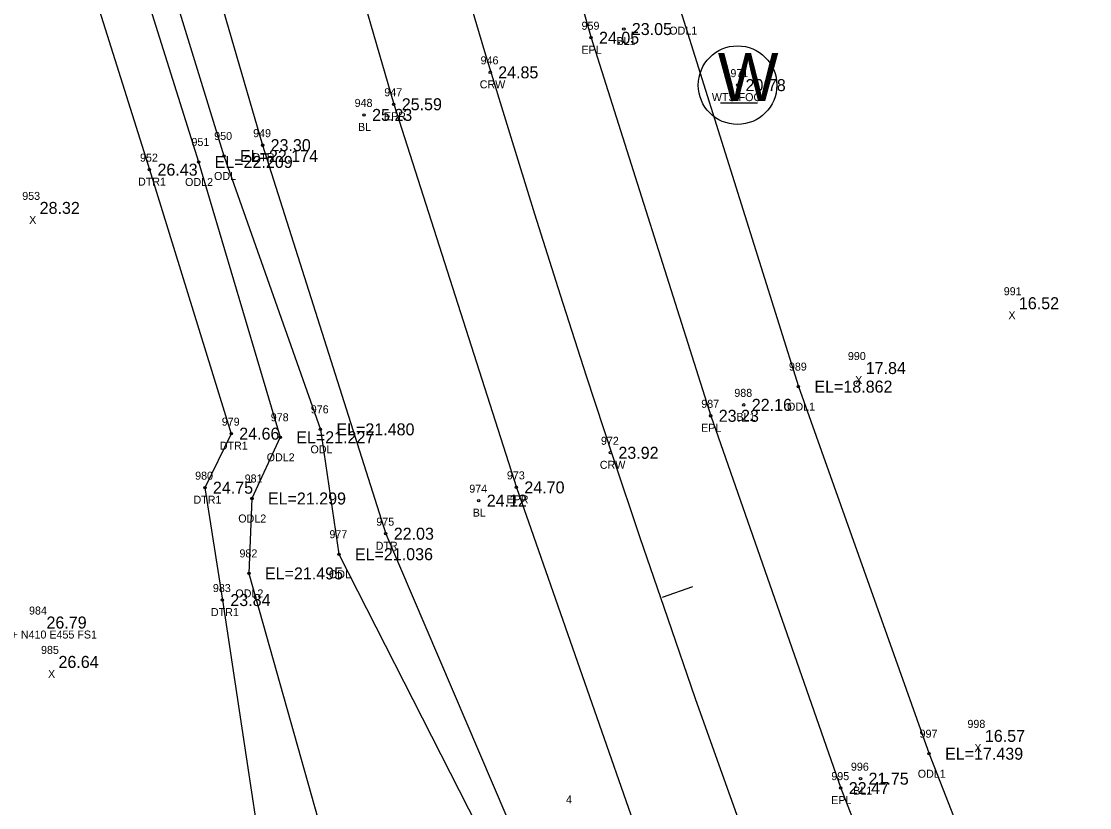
# Model space of a CAD drawing. Extents: x 2042117 to 2045853, y 303080 to 309569.
# Drawn here: x 2042863.2 to 2042996.7, y 306702 to 306800.2 of the extents above; entities that cross this region are included whole.
import ezdxf

# ---------------------------------------------------------------- set-up
doc = ezdxf.new("R2010")
doc.units = 0
for name, color, linetype in [('RD_DTM_BkLn_txCode', 7, 'Continuous'), ('RD_EX_H2O', 7, 'Continuous'), ('RD_EX_H2O_txCode', 7, 'Continuous'), ('RD_EX_Misc_txCode', 7, 'Continuous'), ('RD_EX_Road', 7, 'Continuous'), ('RD_EX_Road_txCode', 7, 'Continuous'), ('RD_EX_TX_H2O_ELEV', 7, 'Continuous'), ('RD_EX_TX_Misc_ELEV', 7, 'Continuous'), ('RD_EX_TX_Road_ELEV', 7, 'Continuous'), ('RD_EX_TX_UT_ELEV', 7, 'Continuous'), ('RD_EX_UT', 7, 'Continuous'), ('RD_EX_UT_txCode', 7, 'Continuous'), ('RD_HC_Cl', 7, 'Continuous'), ('RD_HC_Data_Tic', 7, 'Continuous'), ('RD_HC_Survey_ELEV', 7, 'Continuous'), ('RD_HC_Survey_txCode', 7, 'Continuous'), ('RD_SMD_Locator', 7, 'Continuous')]:
    doc.layers.add(name, color=color, linetype=linetype)

msp = doc.modelspace()

# ---------------------------------------------------------------- linework, layer by layer
at = {"layer": 'RD_EX_H2O'}
for points in [[(2042865.43, 307427.05), (2042866.84, 307378.87), (2042866.82, 307329.93), (2042876.23, 307282.16), (2042878.43, 307232.86), (2042875.08, 307184.77), (2042887.19, 307136.65), (2042884.32, 307120.02), (2042882.74, 307087.49), (2042892.51, 307039.16), (2042896.41, 306990.42), (2042899.37, 306973.37), (2042910.05, 306942.23), (2042920.75, 306896.67), (2042927.15, 306846.78), (2042945.6, 306801.59), (2042960.32, 306754.61), (2042976.65, 306708.74), (2042994.63, 306662.76), (2043013.3, 306616.98), (2043029.17, 306571.91), (2043050.77, 306528.53)], [(2042809.74, 307126.16), (2042806.56, 307122.63), (2042790.31, 307116.78), (2042788.49, 307114.78), (2042791.89, 307113.57), (2042804.81, 307114.94), (2042810.25, 307075.93), (2042820.25, 307025.92), (2042830.4, 306977.21), (2042843.29, 306928.12), (2042852.91, 306878.24), (2042864.55, 306828.43), (2042879.23, 306781.72), (2042889.45, 306748.73), (2042886.16, 306741.98), (2042888.34, 306727.94), (2042896.13, 306676.35), (2042885.67, 306665.43), (2042857.25, 306612.72)], [(2042809.74, 307126.16), (2042815.01, 307124.31), (2042821.79, 307118.99), (2042825.8, 307110.2), (2042827.88, 307100.21), (2042830.08, 307078.71), (2042836.25, 307029.11), (2042845.48, 306980.04), (2042852.07, 306929.46), (2042864.58, 306881.26), (2042879.31, 306833.06), (2042893.37, 306784.78), (2042908.76, 306736.23), (2042928.77, 306689.39), (2042938.94, 306669.11)], [(2042812.2, 307117.75), (2042817.66, 307076.99), (2042828.97, 307027.39), (2042840.42, 306978.95), (2042848.44, 306929.66), (2042859.84, 306880.36), (2042873.68, 306831.67), (2042888.54, 306783.43), (2042900.59, 306749.27), (2042902.9, 306733.67), (2042926.04, 306688.21), (2042936.45, 306668.37), (2042947.44, 306643.99), (2042966.18, 306597.91), (2042985.34, 306551.14), (2042987.61, 306538.59)], [(2042810.02, 307117.36), (2042813.87, 307076.18), (2042825.65, 307027), (2042835.99, 306978.45), (2042846.19, 306929.27), (2042857.5, 306879.97), (2042870.3, 306830.67), (2042885.37, 306782.68), (2042895.57, 306748.28), (2042892.03, 306740.63), (2042891.66, 306731.27), (2042905.95, 306680.58), (2042906.87, 306643.18), (2042864.97, 306605.63)]]:
    msp.add_lwpolyline(points, dxfattribs=at)
at = {"layer": 'RD_EX_Road'}
for points in [[(2042921.09, 306844.85), (2042934.41, 306798.2), (2042949.37, 306750.96), (2042965.62, 306704.44), (2042983.48, 306658.43), (2043001.91, 306612.18), (2043021.64, 306567.98), (2043042.58, 306523.81), (2043065.05, 306479.23), (2043088.14, 306436.09), (2043112.53, 306392.81), (2043137.38, 306350.66), (2043162.88, 306309.77)], [(2042895.94, 306837.56), (2042909.76, 306789.89), (2042925.08, 306742.02), (2042941.49, 306695.02), (2042958.75, 306648.66), (2042978.01, 306602.25), (2042998.08, 306556.93), (2043019.38, 306511.63), (2043041.84, 306466.86), (2043065.03, 306422.83), (2043089.72, 306379.65), (2043115.12, 306336.87), (2043141.61, 306295.02)]]:
    msp.add_lwpolyline(points, dxfattribs=at)
at = {"layer": 'RD_EX_UT'}
msp.add_line((2042950.59, 306790.07), (2042955.22, 306790.07), dxfattribs=at)
msp.add_circle((2042952.72, 306792.28), 4.91, dxfattribs=at)
at = {"layer": 'RD_HC_Cl'}
msp.add_arc((2044751.25, 307348.43), 1911.29, 137.68184, 219.86836, dxfattribs=at)
at = {"layer": 'RD_HC_Data_Tic'}
msp.add_line((2042943.35, 306728.32), (2042947.13, 306729.62), dxfattribs=at)
at = {"layer": 'RD_SMD_Locator'}
for centre in [(2042938.51, 306799.29), (2042934.41, 306798.2), (2042921.81, 306793.88), (2042952.72, 306792.28), (2042909.76, 306789.89), (2042906.05, 306788.56), (2042893.37, 306784.78), (2042885.37, 306782.68), (2042888.54, 306783.43), (2042879.23, 306781.72), (2042960.32, 306754.61), (2042953.5, 306752.33), (2042949.37, 306750.96), (2042900.59, 306749.27), (2042889.45, 306748.73), (2042895.57, 306748.28), (2042936.83, 306746.34), (2042886.16, 306741.98), (2042925.08, 306742.02), (2042892.03, 306740.63), (2042920.38, 306740.36), (2042908.76, 306736.23), (2042902.9, 306733.67), (2042891.66, 306731.27), (2042888.34, 306727.94), (2042976.65, 306708.74), (2042968.09, 306705.62), (2042965.62, 306704.44)]:
    msp.add_circle(centre, 0.15, dxfattribs=at)

# ---------------------------------------------------------------- texts
at = {"layer": 'RD_DTM_BkLn_txCode'}
for s, p in [('BL1', (2042937.59, 306797.29)), ('948', (2042904.87, 306789.56)), ('BL', (2042905.29, 306786.56)), ('988', (2042952.32, 306753.33)), ('BL1', (2042952.58, 306750.33)), ('974', (2042919.2, 306741.36)), ('BL', (2042919.63, 306738.36)), ('996', (2042966.89, 306706.62)), ('BL1', (2042967.17, 306703.62))]:
    msp.add_text(s, height=1, dxfattribs=at).set_placement(p)
at = {"layer": 'RD_EX_H2O_txCode'}
for s, p in [('ODL1', (2042944.19, 306798.59)), ('949', (2042892.19, 306785.78)), ('951', (2042884.48, 306784.68)), ('950', (2042887.32, 306785.43)), ('952', (2042878.05, 306782.72)), ('DTR', (2042892.1, 306782.78)), ('ODL', (2042887.3, 306780.43)), ('DTR1', (2042877.8, 306779.72)), ('ODL2', (2042883.68, 306779.68)), ('989', (2042959.14, 306756.61)), ('976', (2042899.39, 306751.27)), ('ODL1', (2042958.91, 306751.61)), ('979', (2042888.27, 306749.73)), ('978', (2042894.39, 306750.28)), ('DTR1', (2042888.02, 306746.73)), ('ODL', (2042899.35, 306746.27)), ('ODL2', (2042893.88, 306745.28)), ('980', (2042884.94, 306742.98)), ('981', (2042891.13, 306742.63)), ('DTR1', (2042884.73, 306739.98)), ('ODL2', (2042890.33, 306737.63)), ('975', (2042907.58, 306737.23)), ('977', (2042901.72, 306735.67)), ('DTR', (2042907.5, 306734.23)), ('982', (2042890.48, 306733.27)), ('ODL', (2042901.66, 306730.67)), ('983', (2042887.16, 306728.94)), ('ODL2', (2042889.97, 306728.27)), ('DTR1', (2042886.91, 306725.94)), ('997', (2042975.47, 306710.74)), ('ODL1', (2042975.24, 306705.74))]:
    msp.add_text(s, height=1, dxfattribs=at).set_placement(p)
at = {"layer": 'RD_EX_Misc_txCode'}
for s, p in [('953', (2042863.33, 306777.94)), ('X', (2042864.2, 306774.94)), ('991', (2042985.99, 306766.03)), ('X', (2042986.57, 306763.03)), ('990', (2042966.51, 306757.93)), ('X', (2042967.42, 306754.93)), ('984', (2042864.18, 306726.13)), ('MSP FLAG + N410 E455 FS1', (2042854.87, 306723.13)), ('985', (2042865.68, 306721.21)), ('X', (2042866.55, 306718.21)), ('998', (2042981.45, 306711.97)), ('X', (2042982.32, 306708.97))]:
    msp.add_text(s, height=1, dxfattribs=at).set_placement(p)
at = {"layer": 'RD_EX_Road_txCode'}
for s, p in [('959', (2042933.23, 306799.2)), ('EPL', (2042933.21, 306796.2)), ('947', (2042908.58, 306790.89)), ('EPR', (2042908.53, 306787.89)), ('987', (2042948.19, 306751.96)), ('EPL', (2042948.17, 306748.96)), ('973', (2042923.9, 306743.02)), ('EPR', (2042923.85, 306740.02)), ('995', (2042964.44, 306705.44)), ('EPL', (2042964.42, 306702.44))]:
    msp.add_text(s, height=1, dxfattribs=at).set_placement(p)
at = {"layer": 'RD_EX_TX_H2O_ELEV'}
for s, p in [('23.30', (2042894.37, 306784.03)), ('EL=22.174', (2042890.54, 306782.68)), ('EL=22.209', (2042887.37, 306781.93)), ('26.43', (2042880.23, 306780.97)), ('EL=18.862', (2042962.32, 306753.86)), ('24.66', (2042890.45, 306747.98)), ('EL=21.480', (2042902.59, 306748.52)), ('EL=21.227', (2042897.57, 306747.53)), ('24.75', (2042887.16, 306741.23)), ('EL=21.299', (2042894.03, 306739.88)), ('22.03', (2042909.76, 306735.48)), ('EL=21.036', (2042904.9, 306732.92)), ('EL=21.495', (2042893.66, 306730.52)), ('23.84', (2042889.34, 306727.19)), ('EL=17.439', (2042978.65, 306707.99))]:
    msp.add_text(s, height=1.5, dxfattribs=at).set_placement(p)
at = {"layer": 'RD_EX_TX_Misc_ELEV'}
for s, p in [('23.05', (2042939.51, 306798.54)), ('25.23', (2042907.05, 306787.81)), ('28.32', (2042865.51, 306776.19)), ('16.52', (2042987.88, 306764.28)), ('17.84', (2042968.74, 306756.18)), ('22.16', (2042954.5, 306751.58)), ('24.12', (2042921.38, 306739.61)), ('26.79', (2042866.36, 306724.38)), ('26.64', (2042867.86, 306719.46)), ('16.57', (2042983.63, 306710.22)), ('21.75', (2042969.09, 306704.87))]:
    msp.add_text(s, height=1.5, dxfattribs=at).set_placement(p)
at = {"layer": 'RD_EX_TX_Road_ELEV'}
for s, p in [('24.05', (2042935.41, 306797.45)), ('25.59', (2042910.76, 306789.14)), ('23.23', (2042950.37, 306750.21)), ('24.70', (2042926.08, 306741.27)), ('22.47', (2042966.62, 306703.69))]:
    msp.add_text(s, height=1.5, dxfattribs=at).set_placement(p)
at = {"layer": 'RD_EX_TX_UT_ELEV'}
msp.add_text('20.78', height=1.5, dxfattribs=at).set_placement((2042953.72, 306791.53))
at = {"layer": 'RD_EX_UT'}
msp.add_text('W', height=6, dxfattribs=at).set_placement((2042950.26, 306790.28))
at = {"layer": 'RD_EX_UT_txCode'}
for s, p in [('971', (2042951.83, 306793.28)), ('WTS FOC', (2042949.51, 306790.28))]:
    msp.add_text(s, height=1, dxfattribs=at).set_placement(p)
at = {"layer": 'RD_HC_Survey_ELEV'}
for s, p in [('24.85', (2042922.81, 306793.13)), ('23.92', (2042937.83, 306745.59))]:
    msp.add_text(s, height=1.5, dxfattribs=at).set_placement(p)
at = {"layer": 'RD_HC_Survey_txCode'}
for s, p in [('946', (2042920.61, 306794.88)), ('CRW', (2042920.5, 306791.88)), ('972', (2042935.65, 306747.34)), ('CRW', (2042935.51, 306744.34)), ('4', (2042931.29, 306702.52))]:
    msp.add_text(s, height=1, dxfattribs=at).set_placement(p)

doc.saveas('drawing.dxf')
